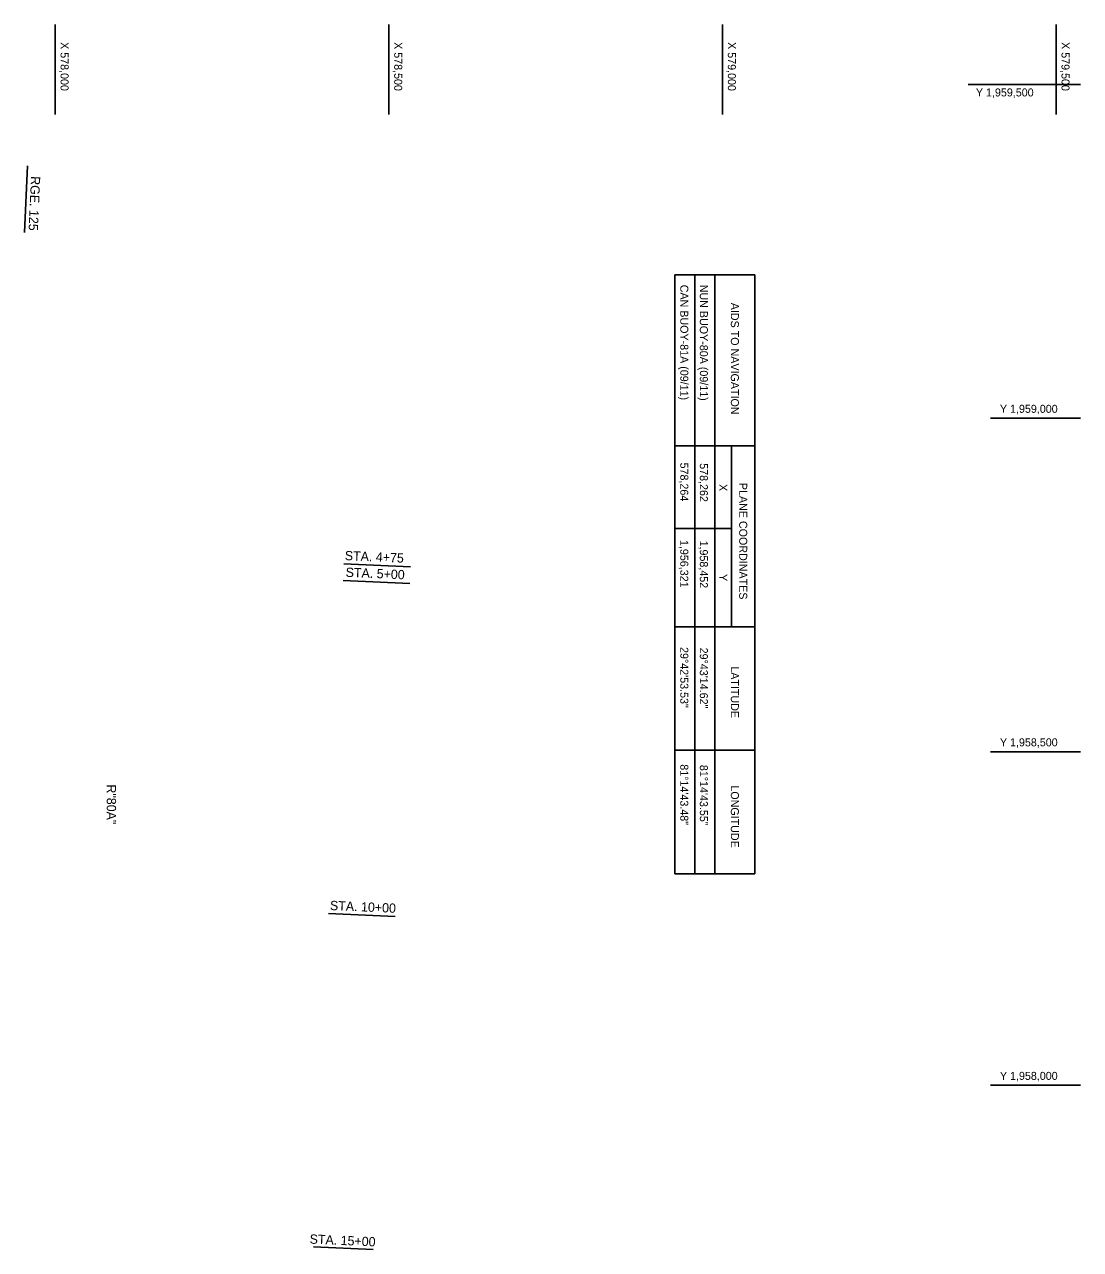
# Model space of a CAD drawing. Extents: x 576588 to 579788, y 1955489 to 1959590.
# Drawn here: x 578205 to 579788, y 1957754 to 1959590 of the extents above; entities that cross this region are included whole.
import ezdxf

# ---------------------------------------------------------------- set-up
doc = ezdxf.new("R2010")
doc.units = 0
for name, color, linetype in [('V-ANNO-NOTE', 7, 'Continuous'), ('V-ANNO-NPLT', 7, 'Continuous'), ('V-ANNO-TEXT', 7, 'Continuous'), ('V-DUCT-MULT', 7, 'Continuous'), ('V-DUCT-MULT-IDEN', 7, 'Continuous')]:
    doc.layers.add(name, color=color, linetype=linetype)

msp = doc.modelspace()

# ---------------------------------------------------------------- linework, layer by layer
at = {"layer": 'V-ANNO-NOTE'}
msp.add_line((578209.7, 1959378.2), (578205.2, 1959278.3), dxfattribs=at)
at = {"layer": 'V-ANNO-NPLT'}
for p, q in [((578683.8, 1958781.7), (578783.7, 1958777.3)), ((578682.7, 1958756.7), (578782.6, 1958752.3)), ((578660.6, 1958257.2), (578760.5, 1958252.8)), ((578638.5, 1957757.7), (578727.9, 1957753.7))]:
    msp.add_line(p, q, dxfattribs=at)
at = {"layer": 'V-DUCT-MULT'}
for p, q in [((578251.3, 1959590.1), (578251.3, 1959455.1)), ((578751.3, 1959590.1), (578751.3, 1959455.1)), ((579251.3, 1959590.1), (579251.3, 1959455.1)), ((579751.3, 1959590.1), (579751.3, 1959455.1)), ((579619.5, 1959500), (579787.8, 1959500)), ((579652.8, 1959000), (579787.8, 1959000)), ((579652.8, 1958500), (579787.8, 1958500)), ((579652.8, 1958000), (579787.8, 1958000))]:
    msp.add_line(p, q, dxfattribs=at)
at = {"layer": 'V-DUCT-MULT-IDEN'}
for p, q in [((579299.8, 1959214.6), (579179.8, 1959214.6)), ((579179.8, 1959214.6), (579179.8, 1958316.7)), ((579209.8, 1959214.6), (579209.8, 1958316.7)), ((579239.8, 1959214.6), (579239.8, 1958316.7)), ((579299.8, 1959214.6), (579299.8, 1958316.7)), ((579299.8, 1958958.3), (579179.8, 1958958.3)), ((579264.8, 1958958.3), (579264.8, 1958687.4)), ((579264.8, 1958834.8), (579179.8, 1958834.8)), ((579299.8, 1958687.4), (579179.8, 1958687.4)), ((579299.8, 1958502.1), (579179.8, 1958502.1)), ((579179.8, 1958316.7), (579299.8, 1958316.7))]:
    msp.add_line(p, q, dxfattribs=at)

# ---------------------------------------------------------------- texts
at = {"layer": 'V-ANNO-NOTE'}
for s, rotation, p in [('RGE. 125', 267.4686, (578215, 1959363)), ('R"80A"', 270, (578328.5, 1958450.9))]:
    msp.add_text(s, height=13.92, rotation=rotation, dxfattribs=at).set_placement(p)
at = {"layer": 'V-ANNO-NPLT'}
for s, p in [('STA. 4+75', (578685, 1958787.2)), ('STA. 5+00', (578686.3, 1958762.2)), ('STA. 10+00', (578662.8, 1958262.7)), ('STA. 15+00', (578632.3, 1957762.6))]:
    msp.add_text(s, height=13.92, rotation=357.4686, dxfattribs=at).set_placement(p)
at = {"layer": 'V-ANNO-TEXT'}
for s, p in [('X 578,000', (578259.3, 1959563.7)), ('X 578,500', (578759.3, 1959563.7)), ('X 579,000', (579259.3, 1959563.7)), ('X 579,500', (579759.3, 1959563.7))]:
    msp.add_text(s, height=12, rotation=270, dxfattribs=at).set_placement(p)
for s, p in [('Y 1,959,500', (579631, 1959482.3)), ('Y 1,959,000', (579667, 1959008)), ('Y 1,958,500', (579667, 1958508)), ('Y 1,958,000', (579667, 1958008))]:
    msp.add_text(s, height=12, dxfattribs=at).set_placement(p)
at = {"layer": 'V-DUCT-MULT-IDEN'}
for s, p in [('CAN BUOY-81A (09/11)                     578,264             1,956,321                    29°42\'53.53"                   81°14\'43.48"', (579188, 1959200)), ('NUN BUOY-80A (09/11)                     578,262             1,958,452                    29°43\'14.62"                   81°14\'43.55"', (579217.3, 1959200)), ('AIDS TO NAVIGATION', (579263.8, 1959173)), ('X', (579246.3, 1958901.2)), ('PLANE COORDINATES', (579276.3, 1958903)), ('Y', (579246.3, 1958766.3)), ('LATITUDE', (579263.8, 1958628)), ('LONGITUDE', (579263.8, 1958449.5))]:
    msp.add_text(s, height=12, rotation=270, dxfattribs=at).set_placement(p)

doc.saveas('drawing.dxf')
